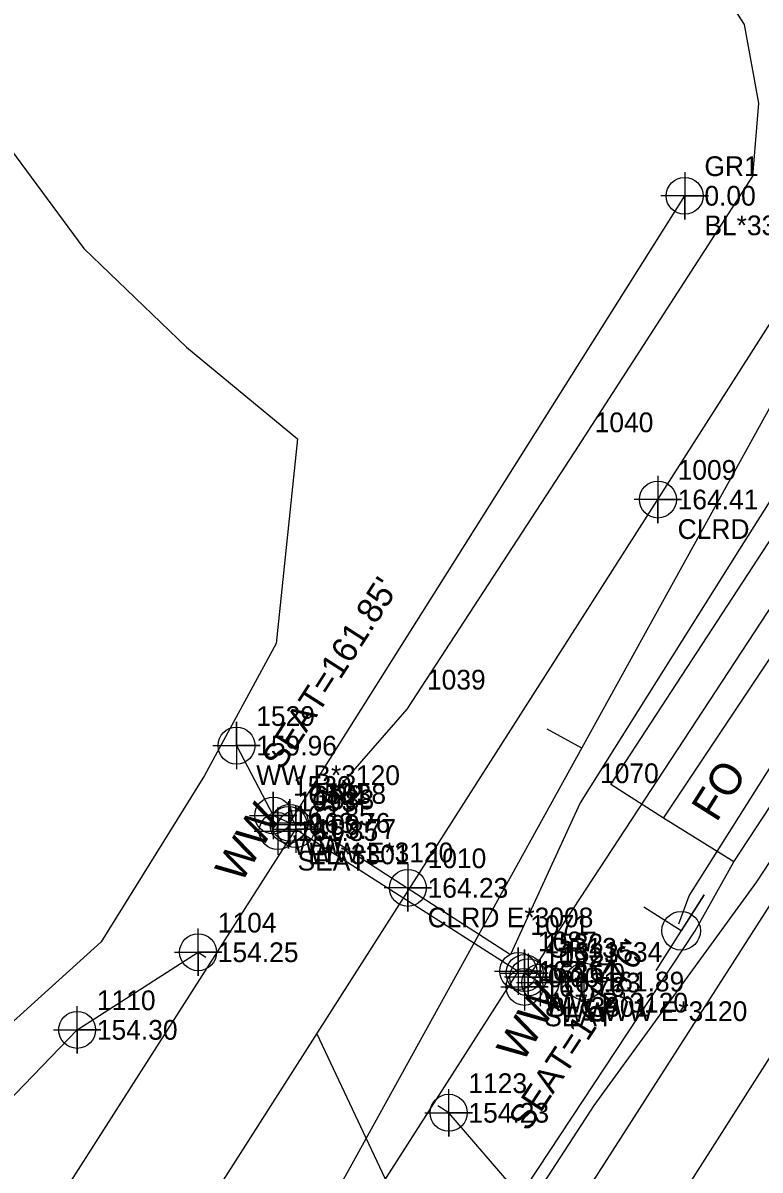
# Model space of a CAD drawing. Extents: x 1840200 to 1849051, y 348278 to 353012.
# Drawn here: x 1844700.4 to 1844793.7, y 350803.3 to 350948.7 of the extents above; entities that cross this region are included whole.
import ezdxf

# ---------------------------------------------------------------- set-up
doc = ezdxf.new("R2010")
doc.units = 0
for name, color, linetype in [('Exist DTM Crownline Cogo Comment', 7, 'Continuous'), ('Exist DTM Crownline Cogo Elevation', 7, 'Continuous'), ('Exist DTM Crownline Cogo Number', 7, 'Continuous'), ('Exist DTM Crownline Cogo Point CELL', 7, 'Continuous'), ('Exist Guardrail', 7, 'Continuous'), ('Exist Guardrail Cogo Comment', 7, 'Continuous'), ('Exist Guardrail Cogo Elevation', 7, 'Continuous'), ('Exist Guardrail Cogo Number', 7, 'Continuous'), ('Exist Guardrail Cogo Point CELL', 7, 'Continuous'), ('Exist Horizontal Alignment', 7, 'Continuous'), ('Exist Horizontal Baseline Alignment', 7, 'Continuous'), ('Exist Horizontal Baseline Alignment Tick small', 7, 'Continuous'), ('Exist Hydro Jurisdictional Stream or Body of Water', 7, 'Continuous'), ('Exist Hydro Stream or Body of Water Cogo Elevation', 7, 'Continuous'), ('Exist Hydro Stream or Body of Water Cogo Number', 7, 'Continuous'), ('Exist Hydro Stream or Body of Water Cogo Point CELL', 7, 'Continuous'), ('Exist Property Tie Line', 7, 'Continuous'), ('Exist Right of Way Line', 7, 'Continuous'), ('Exist Roads EOP', 7, 'Continuous'), ('Exist Roads EOP Cogo Number', 7, 'Continuous'), ('Exist Structure Major Bridge Seat Cogo Comment', 7, 'Continuous'), ('Exist Structure Major Bridge Seat Cogo Elevation', 7, 'Continuous'), ('Exist Structure Major Bridge Seat Cogo Number', 7, 'Continuous'), ('Exist Structure Major Bridge Seat Cogo Point CELL', 7, 'Continuous'), ('Exist Structure Major Bridge Seat Top Elevation', 7, 'Continuous'), ('Exist Structure Major Deck Tunnel Box Culvert', 7, 'Continuous'), ('Exist Structure Major Deck Tunnel Box Culvert Cogo Elevation', 7, 'Continuous'), ('Exist Structure Major Deck Tunnel Box Culvert Cogo Number', 7, 'Continuous'), ('Exist Structure Major Deck Tunnel Box Culvert Cogo Point CELL', 7, 'Continuous'), ('Exist Structure Minor Head and End Wall', 7, 'Continuous'), ('Exist Structure Minor Head and End Wall Cogo Comment', 7, 'Continuous'), ('Exist Structure Minor Head and End Wall Cogo Elevation', 7, 'Continuous'), ('Exist Structure Minor Head and End Wall Cogo Number', 7, 'Continuous'), ('Exist Structure Minor Head and End Wall Cogo Point CELL', 7, 'Continuous'), ('Exist Structure Minor Head and End Wall Text', 7, 'Continuous'), ('Exist Utilities Power Joint Use Telephone CELL', 7, 'Continuous'), ('Exist Utilities Telephone UG Cable', 7, 'Continuous'), ('Exist Utilities Telephone UG Conduit SUE', 7, 'Continuous'), ('Exist Utilities Telephone UG Conduit SUE Text', 7, 'Continuous'), ('Exist Utilities Water UG Line SUE', 7, 'Continuous'), ('Exist Vegetation Woods Line', 7, 'Continuous')]:
    doc.layers.add(name, color=color, linetype=linetype)

# ---------------------------------------------------------------- blocks, each defined once
blk = doc.blocks.new('EXIST DTM CROWNLINE COGO POINT')
at = {"layer": 'Exist DTM Crownline Cogo Point CELL'}
blk.add_lwpolyline([(0, 0.06), (0, -0.06), (0, 0), (0.06, 0), (-0.06, 0)], dxfattribs=at)
blk.add_circle((0, 0), 0.0469, dxfattribs=at)
blk = doc.blocks.new('EXIST STRUCTURE MAJOR BRIDGE SEAT COGO POINT')
at = {"layer": 'Exist Structure Major Bridge Seat Cogo Point CELL'}
blk.add_lwpolyline([(-0.06, 0), (0.06, 0), (0, 0), (0, 0.06), (0, -0.06)], dxfattribs=at)
blk.add_circle((0, 0), 0.0469, dxfattribs=at)
blk = doc.blocks.new('EXIST HYDRO STREAM OR BODY OF WATER COGO POINT')
at = {"layer": 'Exist Hydro Stream or Body of Water Cogo Point CELL'}
blk.add_lwpolyline([(-0.06, 0), (0.06, 0), (0, 0), (0, -0.06), (0, 0.06)], dxfattribs=at)
blk.add_circle((0, 0), 0.0469, dxfattribs=at)
blk = doc.blocks.new('EXIST STRUCTURE MINOR HEAD AND END WALL COGO POINT')
at = {"layer": 'Exist Structure Minor Head and End Wall Cogo Point CELL'}
blk.add_lwpolyline([(-0.06, 0), (0.06, 0), (0, 0), (0, 0.06), (0, -0.06)], dxfattribs=at)
blk.add_circle((0, 0), 0.0469, dxfattribs=at)
blk = doc.blocks.new('EXIST STRUCTURE MAJOR DECK TUNNEL BOX CULVERT COGO POINT')
at = {"layer": 'Exist Structure Major Deck Tunnel Box Culvert Cogo Point CELL'}
blk.add_lwpolyline([(-0.06, 0), (0.06, 0), (0, 0), (0, 0.06), (0, -0.06)], dxfattribs=at)
blk.add_circle((0, 0), 0.0469, dxfattribs=at)
blk = doc.blocks.new('EXIST UTILITIES POWER JOINT USE TELEPHONE')
at = {"layer": 'Exist Utilities Power Joint Use Telephone CELL'}
blk.add_line((0, 0), (0, 0), dxfattribs=at)
blk.add_lwpolyline([(-0.1188, 0), (0.108, -0.0008), (0, -0.0004), (0, 0.1125)], dxfattribs=at)
blk.add_circle((0, 0.0001), 0.049, dxfattribs=at)

msp = doc.modelspace()

# ---------------------------------------------------------------- linework, layer by layer
at = {"layer": 'Exist Guardrail'}
msp.add_line((1844734.02, 350847.08), (1844784.2, 350926.81), dxfattribs=at)
msp.add_lwpolyline([(1844851.85, 350957.61), (1844819.23, 350911.51), (1844764.37, 350827.75)], dxfattribs=at)
at = {"layer": 'Exist Guardrail Cogo Point CELL'}
for points in [[(1844784.2, 350929.81), (1844784.2, 350923.81), (1844784.2, 350926.81), (1844787.2, 350926.81), (1844781.2, 350926.81)], [(1844734.02, 350850.08), (1844734.02, 350844.08), (1844734.02, 350847.08), (1844737.02, 350847.08), (1844731.02, 350847.08)], [(1844764.37, 350830.75), (1844764.37, 350824.75), (1844764.37, 350827.75), (1844767.37, 350827.75), (1844761.37, 350827.75)]]:
    msp.add_lwpolyline(points, dxfattribs=at)
for centre in [(1844784.2, 350926.81), (1844734.02, 350847.08), (1844764.37, 350827.75)]:
    msp.add_circle(centre, 2.34, dxfattribs=at)
at = {"layer": 'Exist Horizontal Alignment'}
msp.add_line((1844418.91, 350320.78), (1844832.24, 350969.01), dxfattribs=at)
at = {"layer": 'Exist Horizontal Baseline Alignment'}
msp.add_line((1844672.71, 350678.49), (1845002.14, 351275.18), dxfattribs=at)
at = {"layer": 'Exist Horizontal Baseline Alignment Tick small'}
msp.add_line((1844771.16, 350856.81), (1844766.78, 350859.22), dxfattribs=at)
at = {"layer": 'Exist Hydro Jurisdictional Stream or Body of Water'}
for points in [[(1844651.64, 350786.02), (1844675.83, 350788.5), (1844707.23, 350821.09), (1844722.55, 350830.93), (1844723.52, 350830.3)], [(1844685.43, 350438.65), (1844695.82, 350440.85), (1844718.62, 350445.67), (1844744.24, 350505.15), (1844747.14, 350559.4), (1844754.2, 350598.17), (1844784.35, 350637.07), (1844806.33, 350724.3), (1844791.7, 350751.83), (1844775.16, 350786.41), (1844754.3, 350810.58), (1844752.94, 350811.45)]]:
    msp.add_lwpolyline(points, dxfattribs=at)
at = {"layer": 'Exist Property Tie Line'}
msp.add_line((1844737.6, 350820.58), (1844762.81, 350767.12), dxfattribs=at)
at = {"layer": 'Exist Right of Way Line'}
msp.add_line((1844461.07, 350293.9), (1844874.4, 350942.13), dxfattribs=at)
at = {"layer": 'Exist Roads EOP'}
for points in [[(1845029.44, 351254.68), (1845007.69, 351220.68), (1844980.5, 351178.01), (1844953.56, 351135.84), (1844927.19, 351094.43), (1844899.65, 351051.72), (1844872.25, 351009.01), (1844845.41, 350966.05), (1844818.24, 350924.9), (1844791.16, 350882.01), (1844770.98, 350849.87), (1844762.14, 350830.63)], [(1844736.43, 350847.25), (1844749.05, 350861.73), (1844770.3, 350894.35), (1844792.85, 350929.32), (1844793.59, 350938.58), (1844791.79, 350948.52), (1844786.43, 350956.91)], [(1844736.43, 350847.25), (1844762.14, 350830.63)]]:
    msp.add_lwpolyline(points, dxfattribs=at)
at = {"layer": 'Exist Structure Major Deck Tunnel Box Culvert'}
msp.add_lwpolyline([(1844648.1, 350710.56), (1844734.92, 350846.55), (1844763.11, 350828.55), (1844676.15, 350692.59), (1844648.1, 350710.56)], dxfattribs=at)
at = {"layer": 'Exist Structure Minor Head and End Wall'}
for points in [[(1844727.42, 350857.12), (1844732.08, 350848.26), (1844734.18, 350847.33)], [(1844763.92, 350828.29), (1844765.91, 350827.08), (1844771.43, 350827.21)]]:
    msp.add_lwpolyline(points, dxfattribs=at)
at = {"layer": 'Exist Utilities Telephone UG Cable'}
for points in [[(1844781.52, 350847.91), (1844774.84, 350852.19), (1844828.2, 350934), (1844980.52, 351171.7), (1845059.17, 351296.08)], [(1844346.44, 350151.45), (1844341.26, 350155.73), (1844478.11, 350373.12), (1844653.01, 350645.77), (1844660.65, 350640.87), (1844715.71, 350727.83), (1844785.54, 350833.66), (1844790.43, 350842.4), (1844781.52, 350847.91), (1844890.71, 351011.88), (1845027.38, 351230.56), (1845029.36, 351233.76), (1845056.36, 351221.55), (1845032.73, 351239.39), (1845066.03, 351291.24)], [(1844331.53, 350112.62), (1844354.74, 350149.21), (1844815.08, 350868.27), (1844864.7, 350947.73), (1845038.47, 351224.2), (1845056.36, 351221.55), (1845046.68, 351237.02), (1845077.41, 351286.63)], [(1844790.43, 350842.4), (1844831.38, 350904.81), (1844886.06, 350987.05), (1844965.83, 351113.23), (1845037.43, 351227.38), (1845056.36, 351221.55), (1845042.85, 351236.13), (1845074.32, 351286.64)]]:
    msp.add_lwpolyline(points, dxfattribs=at)
at = {"layer": 'Exist Utilities Telephone UG Conduit SUE'}
msp.add_lwpolyline([(1844783.45, 350834.55), (1844784.78, 350838.07), (1844796.15, 350856.09), (1844803.36, 350871.73), (1844816.2, 350888.2), (1844834.06, 350916.27), (1844836.81, 350920.07), (1844850.12, 350940.23), (1844870.69, 350971.18)], dxfattribs=at)
at = {"layer": 'Exist Utilities Water UG Line SUE'}
msp.add_lwpolyline([(1844615.42, 350593.11), (1844652.79, 350651.56), (1844678.12, 350657.97), (1844679, 350658.28), (1844679.2, 350658.91), (1844688.96, 350678.16), (1844703.02, 350703.95), (1844712.42, 350719.28), (1844723.85, 350736.18), (1844772.75, 350811.52), (1844793.33, 350839.86), (1844806.55, 350860.02), (1844807.89, 350862.26), (1844812.47, 350868.84), (1844812.76, 350869.4), (1844812.25, 350870.1), (1844806.09, 350891.76), (1844805.98, 350892.36), (1844806.31, 350893.29), (1844818.47, 350912.44), (1844840.28, 350944.51), (1844863.37, 350979.98)], dxfattribs=at)
at = {"layer": 'Exist Vegetation Woods Line'}
msp.add_lwpolyline([(1844646.48, 351140.6), (1844660.62, 351114.96), (1844661.94, 351070.03), (1844683.12, 351028.55), (1844690.75, 351011.9), (1844697.55, 350993), (1844687.95, 350970.86), (1844689.48, 350956.93), (1844696.11, 350936.27), (1844708.08, 350920.13), (1844721.1, 350907.63), (1844735.15, 350896.02), (1844732.46, 350870.06), (1844723.35, 350853.35), (1844710.26, 350832.26), (1844679.51, 350804.43), (1844666.72, 350795.53), (1844655.26, 350795.9)], dxfattribs=at)

# ---------------------------------------------------------------- block references
at = {"layer": 'Exist DTM Crownline Cogo Point CELL', "xscale": 50, "yscale": 50}
for p in [(1844780.81, 350888.32), (1844749.13, 350839.09)]:
    msp.add_blockref('EXIST DTM CROWNLINE COGO POINT', p, dxfattribs=at)
at = {"layer": 'Exist Hydro Stream or Body of Water Cogo Point CELL', "xscale": 50, "yscale": 50}
for p in [(1844722.55, 350830.93), (1844707.23, 350821.09), (1844754.3, 350810.58)]:
    msp.add_blockref('EXIST HYDRO STREAM OR BODY OF WATER COGO POINT', p, dxfattribs=at)
at = {"layer": 'Exist Structure Major Bridge Seat Cogo Point CELL', "xscale": 50, "yscale": 50}
for p in [(1844732.65, 350846.29), (1844763.91, 350826.54)]:
    msp.add_blockref('EXIST STRUCTURE MAJOR BRIDGE SEAT COGO POINT', p, dxfattribs=at)
at = {"layer": 'Exist Structure Major Deck Tunnel Box Culvert Cogo Point CELL', "xscale": 50, "yscale": 50}
for p in [(1844734.92, 350846.55), (1844763.11, 350828.55)]:
    msp.add_blockref('EXIST STRUCTURE MAJOR DECK TUNNEL BOX CULVERT COGO POINT', p, dxfattribs=at)
at = {"layer": 'Exist Structure Minor Head and End Wall Cogo Point CELL', "xscale": 50, "yscale": 50}
for p in [(1844727.42, 350857.12), (1844732.08, 350848.26), (1844734.18, 350847.33), (1844763.92, 350828.29), (1844765.91, 350827.08), (1844771.43, 350827.21)]:
    msp.add_blockref('EXIST STRUCTURE MINOR HEAD AND END WALL COGO POINT', p, dxfattribs=at)
at = {"layer": 'Exist Utilities Power Joint Use Telephone CELL', "xscale": 50.00000000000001, "yscale": 50, "rotation": 57.60968839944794}
msp.add_blockref('EXIST UTILITIES POWER JOINT USE TELEPHONE', (1844783.76, 350833.65), dxfattribs=at)

# ---------------------------------------------------------------- texts
at = {"layer": 'Exist DTM Crownline Cogo Comment'}
for s, p in [('CLRD', (1844783.31, 350883.32)), ('CLRD E*3008', (1844751.63, 350834.09))]:
    msp.add_text(s, height=2.5, dxfattribs=at).set_placement(p)
at = {"layer": 'Exist DTM Crownline Cogo Elevation'}
for s, p in [('164.41', (1844783.31, 350887.07)), ('164.23', (1844751.63, 350837.84))]:
    msp.add_text(s, height=2.5, dxfattribs=at).set_placement(p)
at = {"layer": 'Exist DTM Crownline Cogo Number'}
for s, p in [('1009', (1844783.31, 350890.82)), ('1010', (1844751.63, 350841.59))]:
    msp.add_text(s, height=2.5, dxfattribs=at).set_placement(p)
at = {"layer": 'Exist Guardrail Cogo Comment'}
for s, p in [('BL*3301', (1844786.7, 350921.82)), ('EL*3301', (1844736.52, 350842.08)), ('BL*3301', (1844766.87, 350822.75))]:
    msp.add_text(s, height=2.5, dxfattribs=at).set_placement(p)
at = {"layer": 'Exist Guardrail Cogo Elevation'}
for p in [(1844786.7, 350925.57), (1844736.52, 350845.83), (1844766.87, 350826.5)]:
    msp.add_text('0.00', height=2.5, dxfattribs=at).set_placement(p)
at = {"layer": 'Exist Guardrail Cogo Number'}
for s, p in [('GR1', (1844786.7, 350929.32)), ('GR2', (1844736.52, 350849.58)), ('GR13', (1844766.87, 350830.25))]:
    msp.add_text(s, height=2.5, dxfattribs=at).set_placement(p)
at = {"layer": 'Exist Hydro Stream or Body of Water Cogo Elevation'}
for s, p in [('154.25', (1844725.05, 350829.68)), ('154.30', (1844709.73, 350819.84)), ('154.23', (1844756.8, 350809.33))]:
    msp.add_text(s, height=2.5, dxfattribs=at).set_placement(p)
at = {"layer": 'Exist Hydro Stream or Body of Water Cogo Number'}
for s, p in [('1104', (1844725.05, 350833.43)), ('1110', (1844709.73, 350823.59)), ('1123', (1844756.8, 350813.08))]:
    msp.add_text(s, height=2.5, dxfattribs=at).set_placement(p)
at = {"layer": 'Exist Roads EOP Cogo Number'}
for s, p in [('1040', (1844772.8, 350896.85)), ('1039', (1844751.55, 350864.23)), ('1070', (1844773.48, 350852.37)), ('1038', (1844738.93, 350849.75)), ('1071', (1844764.64, 350833.13))]:
    msp.add_text(s, height=2.5, dxfattribs=at).set_placement(p)
at = {"layer": 'Exist Structure Major Bridge Seat Cogo Comment'}
for p in [(1844735.15, 350841.29), (1844766.41, 350821.54)]:
    msp.add_text('SEAT', height=2.5, dxfattribs=at).set_placement(p)
at = {"layer": 'Exist Structure Major Bridge Seat Cogo Elevation'}
for s, p in [('161.85', (1844735.15, 350845.04)), ('161.76', (1844766.41, 350825.29))]:
    msp.add_text(s, height=2.5, dxfattribs=at).set_placement(p)
at = {"layer": 'Exist Structure Major Bridge Seat Cogo Number'}
for s, p in [('1093', (1844735.15, 350848.79)), ('1092', (1844766.41, 350829.04))]:
    msp.add_text(s, height=2.5, dxfattribs=at).set_placement(p)
at = {"layer": 'Exist Structure Major Bridge Seat Top Elevation'}
for s, rotation, p in [("SEAT=161.85'", 57.3362, (1844733.17, 350853.86)), ("SEAT=161.76'", 56.754, (1844764.37, 350808.08))]:
    msp.add_text(s, height=3.2, rotation=rotation, dxfattribs=at).set_placement(p)
at = {"layer": 'Exist Structure Major Deck Tunnel Box Culvert Cogo Elevation'}
for s, p in [('163.77', (1844737.42, 350845.3)), ('163.61', (1844765.61, 350827.3))]:
    msp.add_text(s, height=2.5, dxfattribs=at).set_placement(p)
at = {"layer": 'Exist Structure Major Deck Tunnel Box Culvert Cogo Number'}
for s, p in [('1088', (1844737.42, 350849.05)), ('1087', (1844765.61, 350831.05))]:
    msp.add_text(s, height=2.5, dxfattribs=at).set_placement(p)
at = {"layer": 'Exist Structure Minor Head and End Wall Cogo Comment'}
for s, p in [('WW B*3120', (1844729.92, 350852.12)), ('WW', (1844734.58, 350843.26)), ('WW E*3120', (1844736.68, 350842.33)), ('WW B*3120', (1844766.42, 350823.29)), ('WW', (1844768.41, 350822.08)), ('WW E*3120', (1844773.93, 350822.21))]:
    msp.add_text(s, height=2.5, dxfattribs=at).set_placement(p)
at = {"layer": 'Exist Structure Minor Head and End Wall Cogo Elevation'}
for s, p in [('159.96', (1844729.92, 350855.87)), ('163.85', (1844734.58, 350847.01)), ('163.76', (1844736.68, 350846.08)), ('163.70', (1844766.42, 350827.04)), ('163.73', (1844768.41, 350825.83)), ('161.89', (1844773.93, 350825.96))]:
    msp.add_text(s, height=2.5, dxfattribs=at).set_placement(p)
at = {"layer": 'Exist Structure Minor Head and End Wall Cogo Number'}
for s, p in [('1529', (1844729.92, 350859.62)), ('1530', (1844734.58, 350850.76)), ('1531', (1844736.68, 350849.83)), ('1532', (1844766.42, 350830.79)), ('1533', (1844768.41, 350829.58)), ('1534', (1844773.93, 350829.71))]:
    msp.add_text(s, height=2.5, dxfattribs=at).set_placement(p)
at = {"layer": 'Exist Structure Minor Head and End Wall Text'}
for p in [(1844727.96, 350839.5), (1844763.63, 350816.76)]:
    msp.add_text('WW', height=4, rotation=59.0825, dxfattribs=at).set_placement(p)
at = {"layer": 'Exist Utilities Telephone UG Conduit SUE Text'}
msp.add_text('FO', height=4, rotation=57.7281, dxfattribs=at).set_placement((1844788.23, 350847.29))

doc.saveas('drawing.dxf')
